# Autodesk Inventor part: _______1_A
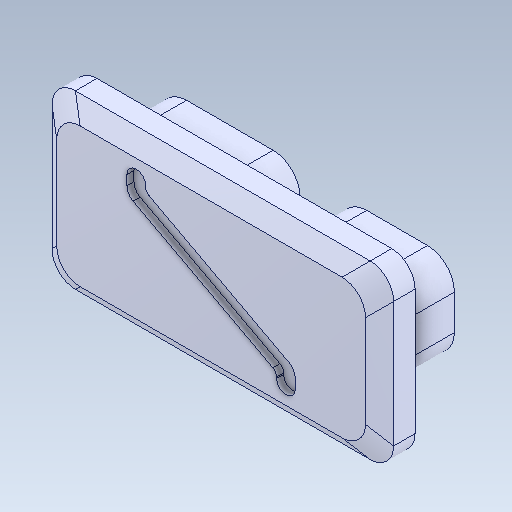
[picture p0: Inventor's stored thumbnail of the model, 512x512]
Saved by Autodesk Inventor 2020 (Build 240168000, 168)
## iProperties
Created: 2017-09
Part Number: _______1_A
Material: Générique
Document SubType Name: Modeling
Designer: bruno
Density: 1 g/cm^3
Appearance: Par défaut
Author: bruno
Sending System: SolidWorks 2016
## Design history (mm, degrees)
feature "Importée1"
node "Solide1"
